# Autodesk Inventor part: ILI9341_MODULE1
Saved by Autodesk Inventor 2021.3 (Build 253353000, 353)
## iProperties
Created: 2021-12
Part Number: ILI9341_MODULE1
Material: Generic
Document SubType Name: Modeling
Designer: Administrator
Density: 1 g/cm^3
Appearance: Default
Title: ILI9341_MODULE1
Author: Administrator
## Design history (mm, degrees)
feature "Body1"
body "Solid1"
